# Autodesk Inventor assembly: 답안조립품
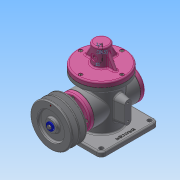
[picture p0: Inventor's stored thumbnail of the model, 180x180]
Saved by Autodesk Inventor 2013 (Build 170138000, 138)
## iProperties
Created: 2020-02
Part Number: 답안조립품
Document SubType Name: Assembly
Designer: Administrator
Mass: 2563.01 g
Surface Area: 2485.59 cm^2
Volume: 789.814 cm^3
Density: 3.24508 g/cm^3
Author: Administrator
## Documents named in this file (21)
- C:\Users\Administrator\Desktop\600206V1003\답안조립품.iam
- C:\Users\Administrator\Desktop\600206V1003\본체.ipt
- C:\Users\Administrator\Desktop\600206V1003\19가변스프링.ipt
- C:\Users\Administrator\Desktop\600206V1003\E-링.ipt
- C:\Users\Administrator\Desktop\600206V1003\Ű 4 x 4 x 25.ipt
- C:\Users\Administrator\Desktop\600206V1003\V-벨트풀리.ipt
- C:\Users\Administrator\Desktop\600206V1003\개스킷 A.ipt
- C:\Users\Administrator\Desktop\600206V1003\개스킷 B.ipt
- C:\Users\Administrator\Desktop\600206V1003\덮개.ipt
- C:\Users\Administrator\Desktop\600206V1003\뒤커버.ipt
- C:\Users\Administrator\Desktop\600206V1003\링크.ipt
- C:\Users\Administrator\Desktop\600206V1003\베어링 17 x 40 x 12.ipt
- C:\Users\Administrator\Desktop\600206V1003\볼트 M4 x 10.ipt
- C:\Users\Administrator\Desktop\600206V1003\슬라이더.ipt
- C:\Users\Administrator\Desktop\600206V1003\앞커버.ipt
- C:\Users\Administrator\Desktop\600206V1003\오일 실 17 30 8.ipt
- C:\Users\Administrator\Desktop\600206V1003\와셔 4x16.ipt
- C:\Users\Administrator\Desktop\600206V1003\육각 소켓 머리 볼트 M4 x 10.ipt
- C:\Users\Administrator\Desktop\600206V1003\클레비스 핀 6 x 22.ipt
- 클레비스 핀 6 x 22.ipt
- C:\Users\Administrator\Desktop\600206V1003\편심축.ipt
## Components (7 placed, 6 different names)
1. 19가변스프링:1
2. E-링:1
3. Ű 4 x 4 x 25:1 — 각도:1
4. V-벨트풀리:1
5. 개스킷 A:1
6. 개스킷 B:1
7. 개스킷 A:2
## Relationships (1: Angle 1)
- 각도:1 [Angle]: Ű 4 x 4 x 25:1
